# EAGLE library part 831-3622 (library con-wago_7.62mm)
Serie 831, Stiftleiste (für Leiterplatten) mit abgewinkelten Einlötstiften / Series 831, Male header (for PCBs) with angled solder pins Polzahl / Pole No.: 2 Bemessungsspannung / Rated Voltage: 630 V Nennstrom / Nominal Current: 41 A Lötstiftlänge: / Solder Pin Length: 4 mm Farbe / Color: lichtgrau / light gray Stand: 01.01.2012. Die jeweils aktuellen Daten zu diesem Artikel finden Sie in unserem Produktkatalog, den Sie unter www.wago.com einsehen können. As of: 01/01/2012. Please find the newest data for this article in our product catalogue, which can be viewed under www.wago.com.
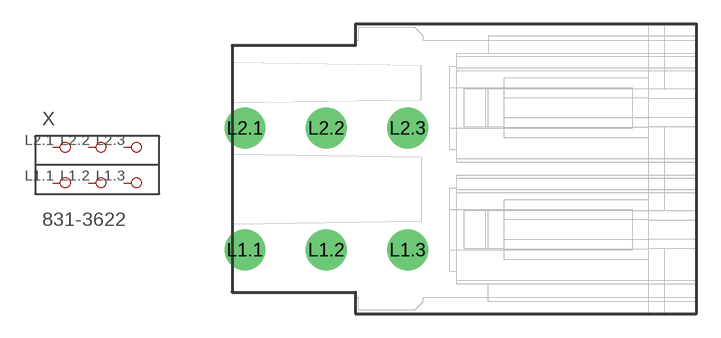
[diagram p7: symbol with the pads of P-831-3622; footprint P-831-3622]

Designator prefix X

## 831-3622  [P-831-3622]
L1.1  P1.1
L1.2  P1.2
L1.3  P1.3
L2.1  P2.1
L2.2  P2.2
L2.3  P2.3

## Footprint P-831-3622 (pad centres in mm)
drill 1.7 round: L1.1 -13.7,-5.06; L1.2 -8.62,-5.06; L1.3 -3.54,-5.06; L2.1 -13.7,2.56; L2.2 -8.62,2.56; L2.3 -3.54,2.56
